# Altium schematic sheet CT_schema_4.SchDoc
size 368 x 245 mm
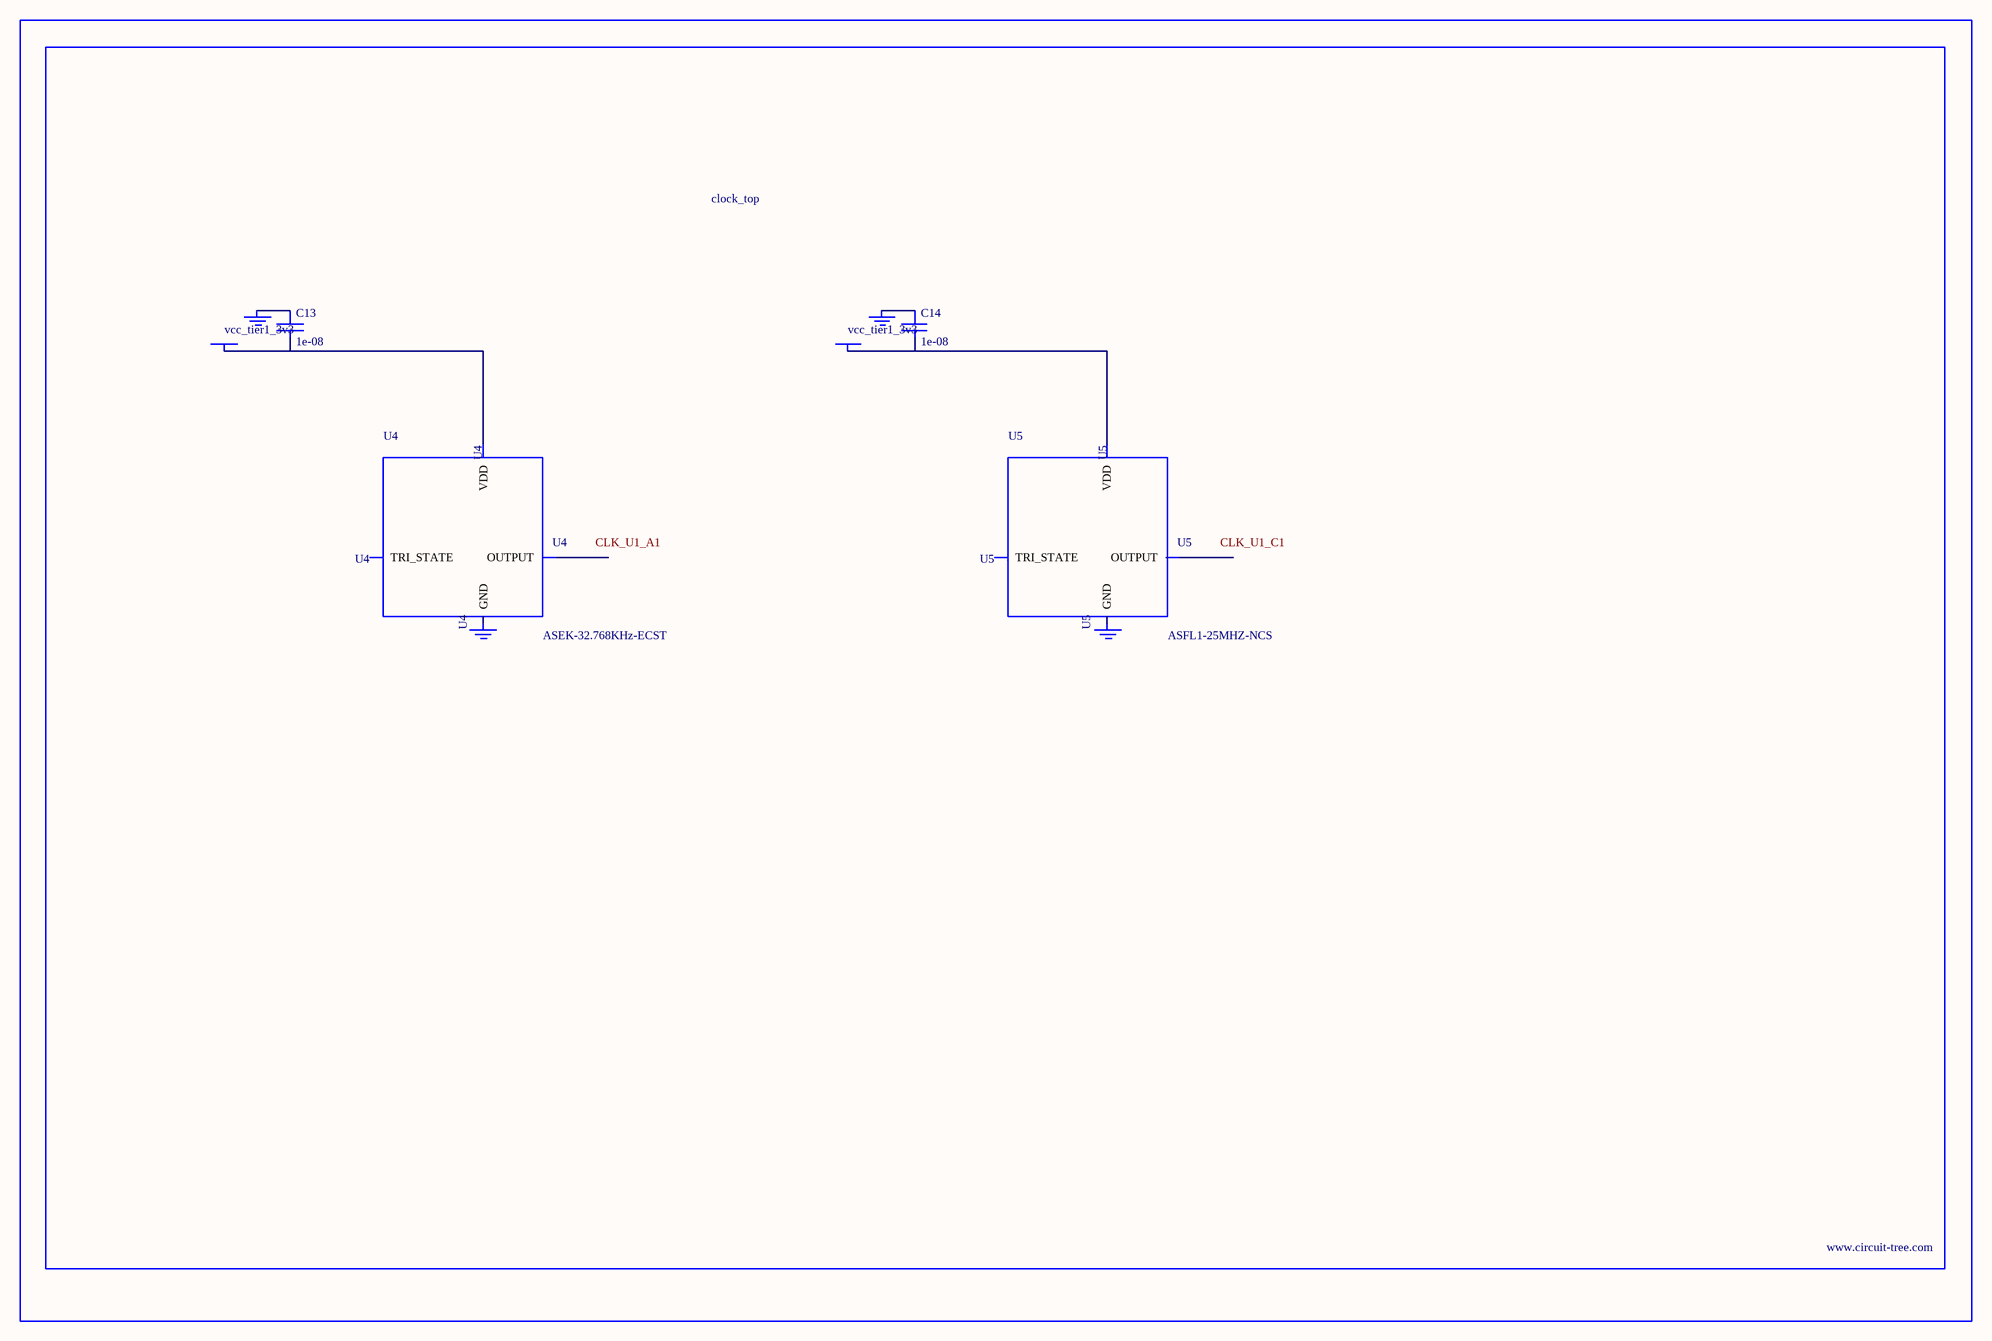
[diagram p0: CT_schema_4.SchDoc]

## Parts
BORDER3  (no value)
C13  1e-08  [C0402]
C14  1e-08  [C0402]
GND_INSTANCE_3_0  (no value)
GND_INSTANCE_3_1  (no value)
GND_INSTANCE_3_2  (no value)
GND_INSTANCE_3_3  (no value)
POWER_INSTANCE_3_0  vcc_tier1_3v3
POWER_INSTANCE_3_1  vcc_tier1_3v3
U4  ASEK-32.768KHz-ECST  [ASEK]
U5  ASFL1-25MHZ-NCS  [ASFL1]

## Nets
NetC13_1: C13.1 GND_INSTANCE_3_0.0(GND)
NetC13_2: C13.2 POWER_INSTANCE_3_0.0(PWR) U4.4(VDD)
NetC14_1: C14.1 GND_INSTANCE_3_2.0(GND)
NetC14_2: C14.2 POWER_INSTANCE_3_1.0(PWR) U5.4(VDD)

Not connected (* = marked no-connect by the designer): GND_INSTANCE_3_1 0(GND); GND_INSTANCE_3_3 0(GND); U4 1(TRI_STATE) 2(GND) 3(OUTPUT); U5 1(TRI_STATE) 2(GND) 3(OUTPUT)

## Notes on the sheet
- Labels drawn without touching a wire or pin: CLK_U1_A1, CLK_U1_C1

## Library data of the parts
BORDER3 = BORDER_PAGE3
C13 C14 = C0402C103K3RAC
GND_INSTANCE_3_0-GND_INSTANCE_3_3 = GND
POWER_INSTANCE_3_0 POWER_INSTANCE_3_1 = PWR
